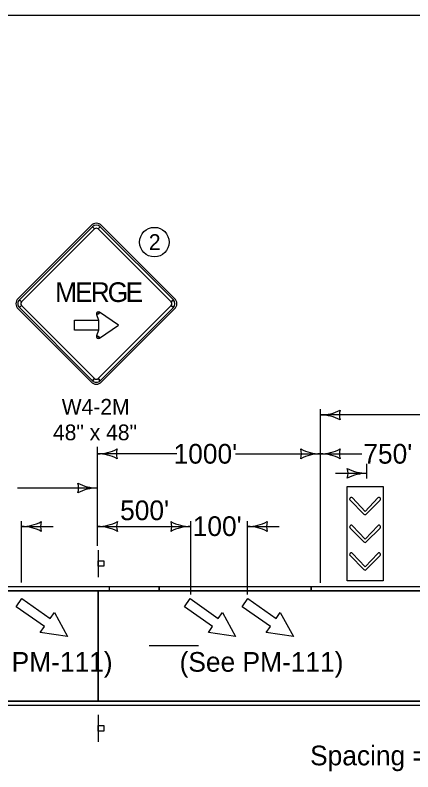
# Model space of a CAD drawing. Extents: x 10133 to 2270741, y 5363 to 1733450.
# Drawn here: x 25305 to 25709, y 9175 to 9944 of the extents above; entities that cross this region are included whole.
import ezdxf

# ---------------------------------------------------------------- set-up
doc = ezdxf.new("R2010")
doc.units = 0
for name, color, linetype in [('dsnNonPlotable', 7, 'Continuous'), ('dsnShtPlotShapeBatchPrint', 7, 'Continuous'), ('dsnStdBorder', 7, 'Continuous'), ('Level 12', 7, 'Continuous'), ('Level 2', 7, 'Continuous'), ('SheetBorder', 7, 'Continuous')]:
    doc.layers.add(name, color=color, linetype=linetype)

msp = doc.modelspace()

# ---------------------------------------------------------------- linework, layer by layer
at = {"layer": 'dsnNonPlotable'}
for p, q in [((24562.66, 9359.06), (25758.9, 9359.06)), ((25306.23, 9342.98), (25311.97, 9351.18)), ((25311.97, 9351.18), (25340.64, 9331.11)), ((25477.04, 9342.98), (25482.78, 9351.18)), ((25482.78, 9351.18), (25511.44, 9331.11)), ((25535.81, 9342.98), (25541.55, 9351.18)), ((25541.55, 9351.18), (25570.21, 9331.11)), ((25334.9, 9322.91), (25306.23, 9342.98)), ((25505.71, 9322.91), (25477.04, 9342.98)), ((25564.48, 9322.91), (25535.81, 9342.98)), ((25340.64, 9331.11), (25344.94, 9337.25)), ((25344.94, 9337.25), (25358.24, 9312.67)), ((25511.44, 9331.11), (25515.74, 9337.25)), ((25515.74, 9337.25), (25529.05, 9312.67)), ((25570.21, 9331.11), (25574.51, 9337.25)), ((25574.51, 9337.25), (25587.82, 9312.67)), ((25330.6, 9316.77), (25334.9, 9322.91)), ((25501.41, 9316.77), (25505.71, 9322.91)), ((25560.18, 9316.77), (25564.48, 9322.91)), ((25358.24, 9312.67), (25330.6, 9316.77)), ((25529.05, 9312.67), (25501.41, 9316.77)), ((25587.82, 9312.67), (25560.18, 9316.77)), ((24554.7, 9247.04), (26172.85, 9247.04))]:
    msp.add_line(p, q, dxfattribs=at)
msp.add_lwpolyline([(25441.38, 9303.46), (25491.38, 9303.46)], dxfattribs=at)
at = {"layer": 'dsnShtPlotShapeBatchPrint'}
msp.add_circle((25446.59, 9713.42), 15, dxfattribs=at)
at = {"layer": 'dsnStdBorder'}
for p, q in [((25382.33, 9730.4), (25308.08, 9656.15)), ((25383.65, 9729.07), (25385.86, 9726.86)), ((25389.4, 9726.86), (25391.61, 9729.07)), ((25467.18, 9656.15), (25392.93, 9730.4)), ((25311.61, 9652.61), (25309.41, 9654.82)), ((25309.41, 9646.87), (25311.61, 9649.08)), ((25465.85, 9654.82), (25463.64, 9652.61)), ((25463.64, 9649.08), (25465.85, 9646.87)), ((25308.08, 9645.54), (25382.33, 9571.3)), ((25389.66, 9640.53), (25390.75, 9642.25)), ((25392.93, 9571.3), (25467.18, 9645.54)), ((25387.73, 9639.89), (25389.66, 9640.53)), ((25389.66, 9617.41), (25387.73, 9618.06)), ((25390.75, 9615.69), (25389.66, 9617.41)), ((25385.86, 9574.83), (25383.65, 9572.62)), ((25391.61, 9572.62), (25389.4, 9574.83)), ((25661.88, 9437.07), (25675.97, 9451.17)), ((25661.88, 9408.84), (25675.97, 9422.93)), ((25389.45, 9400.56), (25389.45, 9373.06)), ((25661.88, 9380.77), (25675.97, 9394.87)), ((25389.45, 9233.06), (25389.45, 9205.56))]:
    msp.add_line(p, q, dxfattribs=at)
for points in [[(25383.65, 9729.07), (25309.41, 9654.82), (25311.61, 9652.61), (25385.86, 9726.86), (25383.65, 9729.07)], [(25465.85, 9654.82), (25391.61, 9729.07), (25389.4, 9726.86), (25463.64, 9652.61), (25465.85, 9654.82)], [(25309.41, 9646.87), (25383.65, 9572.62), (25385.86, 9574.83), (25311.61, 9649.08), (25309.41, 9646.87)], [(25391.61, 9572.62), (25465.85, 9646.87), (25463.64, 9649.08), (25389.4, 9574.83), (25391.61, 9572.62)], [(25409.97, 9628.97), (25390.75, 9642.25), (25389.66, 9640.53), (25387.73, 9639.89), (25389.72, 9633.97), (25389.72, 9623.97), (25387.73, 9618.06), (25389.66, 9617.41), (25390.75, 9615.69), (25409.97, 9628.97)], [(25365.29, 9623.97), (25365.29, 9633.97), (25389.72, 9633.97), (25389.72, 9623.97), (25365.29, 9623.97)], [(25679.05, 9465.22), (25679.05, 9369.22), (25642.34, 9369.22), (25642.34, 9465.22)], [(25389.54, 9384.11), (25389.54, 9389.74), (25395.17, 9389.74), (25395.17, 9384.11)], [(25389.54, 9216.61), (25389.54, 9222.24), (25395.17, 9222.24), (25395.17, 9216.61)]]:
    msp.add_lwpolyline(points, close=True, dxfattribs=at)
for points in [[(25645.39, 9451.2), (25645.44, 9451.15), (25659.53, 9437.06), (25659.54, 9437.05)], [(25673.65, 9453.5), (25673.59, 9453.44), (25660.7, 9439.87), (25647.79, 9453.45)], [(25645.39, 9422.96), (25645.44, 9422.91), (25659.53, 9408.83), (25659.54, 9408.81)], [(25673.65, 9425.27), (25673.59, 9425.2), (25660.7, 9411.63), (25647.79, 9425.22)], [(25673.65, 9397.2), (25673.59, 9397.14), (25660.7, 9383.57), (25647.79, 9397.15)], [(25645.39, 9394.9), (25645.44, 9394.85), (25659.53, 9380.76), (25659.54, 9380.75)]]:
    msp.add_lwpolyline(points, dxfattribs=at)
for centre, radius, start, end in [((25387.63, 9725.09), 7.5, 44.99999, 134.99974), ((25387.63, 9725.09), 5.62, 44.99999, 134.99974), ((25387.63, 9725.09), 2.5, 44.99999, 134.99974), ((25313.38, 9650.85), 7.5, 134.99974, 224.99995), ((25313.38, 9650.85), 5.62, 134.99974, 224.99995), ((25313.38, 9650.85), 2.5, 134.99974, 224.99995), ((25461.87, 9650.85), 2.5, 315.00016, 44.9998), ((25461.87, 9650.85), 5.62, 315.00016, 44.9998), ((25461.87, 9650.85), 7.5, 315.00016, 44.9998), ((25389.66, 9640.53), 2.03, 57.68768, 198.58144), ((25389.66, 9617.41), 2.03, 161.41825, 302.31259), ((25387.63, 9576.6), 5.62, 224.99995, 315.00016), ((25387.63, 9576.6), 2.5, 224.99995, 315.00016), ((25387.63, 9576.6), 7.5, 224.99995, 315.00016), ((25646.58, 9452.34), 1.65, 42.63982, 223.799), ((25674.82, 9452.34), 1.65, 314.71897, 134.90254), ((25660.7, 9438.22), 1.65, 225.39017, 315.83844), ((25646.58, 9424.1), 1.65, 42.63982, 223.799), ((25674.82, 9424.1), 1.65, 314.71897, 134.90254), ((25660.7, 9409.98), 1.65, 225.39017, 315.83844), ((25646.58, 9396.04), 1.65, 42.63982, 223.799), ((25674.82, 9396.04), 1.65, 314.71897, 134.90254), ((25660.7, 9381.92), 1.65, 225.39017, 315.83844)]:
    msp.add_arc(centre, radius, start, end, dxfattribs=at)
at = {"layer": 'Level 12'}
for p, q in [((25615.28, 9367.19), (25615.28, 9543.82)), ((26042.97, 9537.77), (25615.34, 9537.77)), ((25388.78, 9404.83), (25388.78, 9505.47)), ((25469.28, 9498.34), (25388.78, 9498.34)), ((25529.08, 9498.34), (25615.28, 9498.34)), ((25615.28, 9498.34), (25657.25, 9498.34)), ((25662.58, 9473.22), (25662.58, 9488.08)), ((25630.58, 9478.53), (25662.58, 9478.53)), ((25307.68, 9463.6), (25388.78, 9463.6)), ((25311.71, 9367.59), (25311.71, 9430.03)), ((25483.46, 9355.44), (25483.46, 9430.03)), ((25541.29, 9355.44), (25541.29, 9430.03)), ((25311.71, 9424.45), (25343.71, 9424.45)), ((25389.6, 9424.45), (25458.96, 9424.45)), ((25458.96, 9424.45), (25483.46, 9424.45)), ((25541.29, 9424.45), (25573.29, 9424.45))]:
    msp.add_line(p, q, dxfattribs=at)
for centre, radius, start, end in [((25615.34, 9580.27), 42.5, 270, 298.07249), ((25650.98, 9537.77), 16.42, 162.26665, 197.73335), ((25615.34, 9495.27), 42.5, 61.92751, 90), ((25388.78, 9540.84), 42.5, 270, 298.07249), ((25424.42, 9498.34), 16.42, 162.26665, 197.73335), ((25579.64, 9498.34), 16.42, 342.26665, 17.73335), ((25615.28, 9540.84), 42.5, 241.92751, 270), ((25615.28, 9540.84), 42.5, 270, 298.07249), ((25650.91, 9498.34), 16.42, 162.26665, 197.73335), ((25388.78, 9455.84), 42.5, 61.92751, 90), ((25615.28, 9455.84), 42.5, 90, 118.07249), ((25615.28, 9455.84), 42.5, 61.92751, 90), ((25626.94, 9478.53), 16.42, 342.26665, 17.73335), ((25662.58, 9521.03), 42.5, 241.92751, 270), ((25662.58, 9436.03), 42.5, 90, 118.07249), ((25353.15, 9463.6), 16.42, 342.26665, 17.73335), ((25388.78, 9506.1), 42.5, 241.92751, 270), ((25388.78, 9421.1), 42.5, 90, 118.07249), ((25311.71, 9466.95), 42.5, 270, 298.07249), ((25347.35, 9424.45), 16.42, 162.26665, 197.73335), ((25389, 9466.95), 42.5, 270, 298.07249), ((25424.63, 9424.45), 16.42, 162.26665, 197.73335), ((25447.83, 9424.45), 16.42, 342.26665, 17.73335), ((25483.46, 9466.95), 42.5, 241.92751, 270), ((25541.29, 9466.95), 42.5, 270, 298.07249), ((25576.92, 9424.45), 16.42, 162.26665, 197.73335), ((25311.71, 9381.95), 42.5, 61.92751, 90), ((25389, 9381.95), 42.5, 61.92751, 90), ((25483.46, 9381.95), 42.5, 90, 118.07249), ((25541.29, 9381.95), 42.5, 61.92751, 90)]:
    msp.add_arc(centre, radius, start, end, dxfattribs=at)
at = {"layer": 'Level 2'}
for p, q in [((25483.46, 9363.06), (25291.5, 9363.06)), ((25291.5, 9359.06), (25483.46, 9359.06)), ((25389.45, 9247.06), (25389.45, 9359.06)), ((25451.31, 9359.06), (25389.45, 9359.06)), ((25389.45, 9359.06), (25389.45, 9247.06)), ((25451.31, 9363.06), (25400.49, 9363.06)), ((25400.49, 9363.06), (25400.49, 9359.06)), ((25400.49, 9359.06), (25451.31, 9359.06)), ((25605.94, 9363.06), (25451.31, 9363.06)), ((25451.31, 9363.06), (25451.31, 9359.06)), ((25451.31, 9359.06), (25451.31, 9363.06)), ((25451.31, 9359.06), (25605.94, 9359.06)), ((25605.94, 9359.06), (25451.31, 9359.06)), ((25483.46, 9359.06), (25483.46, 9363.06)), ((25605.94, 9359.06), (25605.94, 9363.06)), ((26820.3, 9363.06), (25605.94, 9363.06)), ((25605.94, 9363.06), (25605.94, 9359.06)), ((25817.3, 9359.06), (25605.94, 9359.06)), ((25605.94, 9359.06), (25817.3, 9359.06)), ((25938.21, 9247.06), (24554.68, 9247.06)), ((24554.68, 9247.06), (25389.45, 9247.06)), ((24558.68, 9243.06), (25964.98, 9243.06)), ((24558.68, 9243.06), (25936.49, 9243.06)), ((25389.45, 9247.06), (25938.21, 9247.06))]:
    msp.add_line(p, q, dxfattribs=at)
msp.add_lwpolyline([(25389.45, 9359.06), (25291.5, 9359.06), (25240.68, 9359.06)], dxfattribs=at)
msp.add_lwpolyline([(25451.31, 9359.06), (25605.94, 9359.06), (25605.94, 9363.06), (25451.31, 9363.06)], close=True, dxfattribs=at)
at = {"layer": 'SheetBorder'}
msp.add_lwpolyline([(24532.52, 9944.02), (27667.53, 9944.02), (27667.53, 7924.02), (24532.52, 7924.02)], close=True, dxfattribs=at)

# ---------------------------------------------------------------- texts
at = {"layer": 'dsnShtPlotShapeBatchPrint'}
msp.add_text('2', height=16, dxfattribs=at).set_placement((25440.97, 9705.42))
at = {"layer": 'dsnStdBorder'}
for s, height, p in [('M', 20, (25345.75, 9652.56)), ('E', 20, (25365.95, 9652.56)), ('R', 20, (25381.93, 9652.56)), ('G', 20, (25399.15, 9652.56)), ('E', 20, (25417.32, 9652.56)), ('W4-2M', 16, (25352.46, 9538.1)), ('48" x 48"', 16, (25343.56, 9512.1)), ('(See PM-111)', 20, (25237.67, 9276.92)), ('(See PM-111)', 20, (25472.21, 9276.92))]:
    msp.add_text(s, height=height, dxfattribs=at).set_placement(p)
at = {"layer": 'Level 12'}
for s, p in [("1000'", (25466.1, 9488.34)), ("750'", (25658.88, 9488.34)), ("500'", (25411.77, 9430.91)), ("100'", (25485.54, 9414.82)), ("Spacing = 65'", (25604.77, 9181.83))]:
    msp.add_text(s, height=20, dxfattribs=at).set_placement(p)

doc.saveas('drawing.dxf')
